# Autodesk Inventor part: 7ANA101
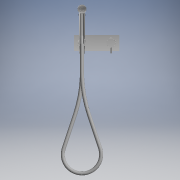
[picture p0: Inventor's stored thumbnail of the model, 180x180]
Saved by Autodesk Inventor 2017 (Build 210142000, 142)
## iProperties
Created: 2021-04
Part Number: 7ANA101
Material: Generico
Document SubType Name: Modeling
Designer: PIZZERA
Density: 1 g/cm^3
Appearance: Default
Author: PIZZERA
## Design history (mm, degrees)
feature "Base4"
node "Solido1"
node "Solido5"
